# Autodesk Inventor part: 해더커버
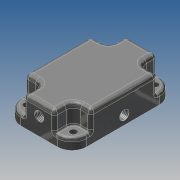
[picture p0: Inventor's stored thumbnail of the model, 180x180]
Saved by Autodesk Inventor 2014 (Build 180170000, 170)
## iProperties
Company: 한국ATC센터
Created: 2014-01
Part Number: 해더커버
Document SubType Name: Modeling
Designer: KYOUNG IL JANG
Density: 2.71 g/cm^3
Material: 알루미늄 6061
Mass: 124.2 g
Surface Area: 122.39 cm^2
Volume: 45.8304 cm^3
Vendor: CBT Solutions
Appearance: 매끄러움 - 중간 회색
Author: KYOUNG IL JANG
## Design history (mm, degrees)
sketch "스케치1"
  geometry: L1 (22.5, -32)-(22.5, 25) reference; L2 (-19.5, -35)-(19.5, -35) reference; L3 (-22.5, 25)-(-22.5, -32) reference; L4 (12.5, 35)-(-12.5, 35) reference; A1 r 10 centre (12.5, 25) between (22.5, 25) and (12.5, 35) reference; A2 r 3 centre (19.5, -32) between (19.5, -35) and (22.5, -32) reference; A3 r 3 centre (-19.5, -32) between (-22.5, -32) and (-19.5, -35) reference; A4 r 10 centre (-12.5, 25) between (-12.5, 35) and (-22.5, 25) reference; 1 further point
extrude "돌출1" new body sketch "스케치1" distance "d0" = 20; taper "d1" = 0 deg
extrude "돌출2" cut sketch "스케치2" distance "d5" = 13; taper "d6" = 0 deg
fillet "모깎기1" dims "d7" = 5
fillet "모깎기2" dims "d8" = 1
fillet "모깎기3" dims "d9" = 2
fillet "모깎기4" dims "d10" = 3
sketch "스케치3"
  geometry: L1 (-21.5, -1)-(-8.5, -1) reference; L2 (10.5, -1)-(23.5, -1) reference; L3 (-32, 0)-(25, 0) reference; L4 (-15, -1)-(-15, 0); L5 (17, -1)-(17, 0); L6 (-2.75, 0)-(-2.75, 7); L7 (-15, 7)-(-2.75, 7); L8 (-15, 0)-(-15, 7); L9 (17, 0)-(17, 7); L10 (4.75, 0)-(4.75, 7); L11 (4.75, 7)-(17, 7); 1 further point
  constraints: 16 end point, 7 parallel, 4 perpendicular, 4 point on line, 2 midpoint, 1 horizontal alignment
  dimensions: "d11" = 8 distance of L5.start L9.end; "d12" = 24.5 diameter of L6 L8; "d13" = 24.5 diameter of L10 L9 (= d12)
  node "참조15"
  node "참조16"
  node "참조17"
revolve "회전1" stored, may be unused: angle "d14" = 90 deg
revolve "회전2" stored, may be unused: angle "d15" = 90 deg
fillet "모깎기5" dims "d16" = 5
sketch "스케치4"
  geometry: C1 r 2.229 at (16, -27.5) reference; C2 r 2.229 at (16, 28.5) reference; C3 r 2.229 at (-16, -27.5) reference; C4 r 2.229 at (-16, 28.5) reference; 1 further point
hole "구멍1" sketch "스케치4" at (16, -27.5), (-16, -27.5), (16, 28.5), (-16, 28.5) diameter "d17" = 4.5; stored, may be unused: countersink angle "d21" = 90 deg, drill point angle "d23" = 118 deg; dims "d18" = 6, "d19" = 4, "d20" = 2, "d22" = 8
sketch "스케치5"
  geometry: L1 (-20.09, 3.496)-(-22.691, 8); L2 (-29.619, 12)-(-37.219, 12); L3 (-35, 0)-(-32, 0) reference; L4 (-35, 8)-(-35, 17) reference; L5 (36.506, 12)-(30.619, 12); L6 (23.691, 8)-(20.656, 2.744); L7 (35, 17)-(35, 8) reference; A1 r 8 centre (-29.619, 4) between (-22.691, 8) and (-29.619, 12); A2 r 8 centre (30.619, 4) between (30.619, 12) and (23.691, 8); 5 further points
  constraints: 8 end point, 8 point on line, 4 point on circle, 4 tangent, 2 centre point, 1 collinear, 1 horizontal, 1 perpendicular
  dimensions: "d24" = 12 distance between parallel lines of L2 L3; "d25" = 10 distance from line of point (-25, 12) L4; "d26" = 120 deg angle of L1 L2; "d27" = 8 radius of A1; "d29" = 9 distance from line of point (26, 12) L7; "d30" = 120 deg angle of L6 L5; "d31" = 8 radius of A2
node "작업점1"
node "작업점2"
hole "구멍2" diameter "d34" = 5.944; stored, may be unused: countersink angle "d40" = 90 deg, drill point angle "d42" = 0 deg; dims "d32" = 10, "d33" = 10, "d35" = 6.886, "d36" = 0.62479, "d37" = 5.959, "d38" = 4, "d39" = 2, "d41" = 6.9
hole "구멍3" diameter "d45" = 5.944; stored, may be unused: countersink angle "d51" = 90 deg, drill point angle "d53" = 0 deg; dims "d43" = 10, "d44" = 10, "d46" = 6.886, "d47" = 0.62479, "d48" = 5.959, "d49" = 4, "d50" = 2, "d52" = 6.9
sketch "스케치6"
  geometry: C1 r 2.972 at (19.5, 12) reference; 1 further point
feature "스윕1" sketch "스케치6" dims "d54" = 0
sketch "스케치7"
  geometry: C1 r 2.972 at (12.5, -12) reference; 1 further point
feature "스윕2" sketch "스케치7" dims "d55" = 0
sketch "스케치8"
  geometry: L1 (0, 36.75)-(0, 61.25) reference; L2 (0, 4.75)-(0, 29.25) reference; L3 (0, 36.75)-(0, 29.25); 3 further points
  constraints: 2 end point, 1 collinear, 1 horizontal alignment, 1 midpoint
  dimensions: "d57" = 6 distance of point (6, 33) point (0, 33)
hole "구멍4" sketch "스케치8" at (6, 33) diameter "d58" = 5.944; stored, may be unused: countersink angle "d64" = 90 deg, drill point angle "d66" = 0 deg; dims "d59" = 6.886, "d60" = 0.62479, "d61" = 5.959, "d62" = 4, "d63" = 2, "d65" = 6.9
sketch "스케치10"
  geometry: C1 r 2.972 at (0, 0) reference; 1 further point
  node "투영된 루프4"
sketch "스케치11"
  geometry: C1 r 2.972 at (0, 0) reference; 1 further point
  node "투영된 루프5"
node "작업축3"
node "작업 평면2"
sketch "스케치12"
  geometry: L1 (3.443, -2.979)-(3.443, 2.98) reference; L2 (3.443, 0)-(11.057, 0); L3 (19.057, -8)-(19.057, -11.414); A1 r 8 centre (11.057, -8) between (19.057, -8) and (11.057, 0); 2 further points
  constraints: 4 end point, 2 perpendicular, 2 point on circle, 2 point on line, 2 tangent, 1 centre point, 1 midpoint, 1 vertical alignment
  dimensions: "d70" = 8 radius of A1
feature "스윕3" sketch "스케치12" dims "d71" = 0
node "작업 평면3"
sketch "스케치13"
  geometry: L1 (34.657, -2.972)-(34.657, 2.972) reference; L2 (34.657, 0)-(27.057, 0); L3 (19.057, 8)-(19.057, 10.673); A1 r 8 centre (27.057, 8) between (19.057, 8) and (27.057, 0); 1 further point
  constraints: 4 end point, 2 perpendicular, 2 point on circle, 2 tangent, 1 centre point, 1 midpoint, 1 point on line
  dimensions: "d73" = 8 radius of A1
feature "스윕4" sketch "스케치13" dims "d74" = 0
feature "면 삭제1"
fillet "모깎기6" dims "d75" = 10
node "솔리드1"
mirror "대칭1"
node "참조1"
node "참조2"
node "참조3"
node "참조4"
node "참조5"
node "참조6"
node "참조7"
node "참조8"
node "참조18"
node "참조19"
node "참조20"
node "참조21"
node "투영된 루프2"
node "투영된 루프3"
other parameters: "d2" = 12, "d3" = 5.5 (derived), "d4" = 5.5, "d69" = -15 deg, "d72" = 15 deg
